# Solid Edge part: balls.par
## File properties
Title: Solid Edge 20
Author: vicky raina
Template: Normal.par
Last saved by: Robert a Rhodes jr
Revision: 7
Application: Solid Edge
Material: aluminum
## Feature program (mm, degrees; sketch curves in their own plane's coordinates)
sketch for "unnamed RevolvedProtrusion 1" plane through (0, 0, 0) normal (0, -1, 0) x-axis (1, 0, 0)
  arc centre (0, 0) radius 6.604 from (0, 6.604) to (0, -6.604) cw
  line (0, 6.604) -> (0, -6.604)
  dimension (radial) = 0
revolve "unnamed RevolvedProtrusion 1" add full turn 360 deg
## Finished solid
Body 1: solid body, 1 face, 0 edges, 0 vertices.
  Faces by surface: sphere 1
Spherical faces by radius (mm): R6.604 x1
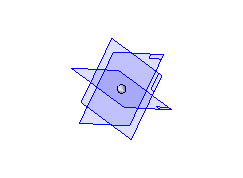
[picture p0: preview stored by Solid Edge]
